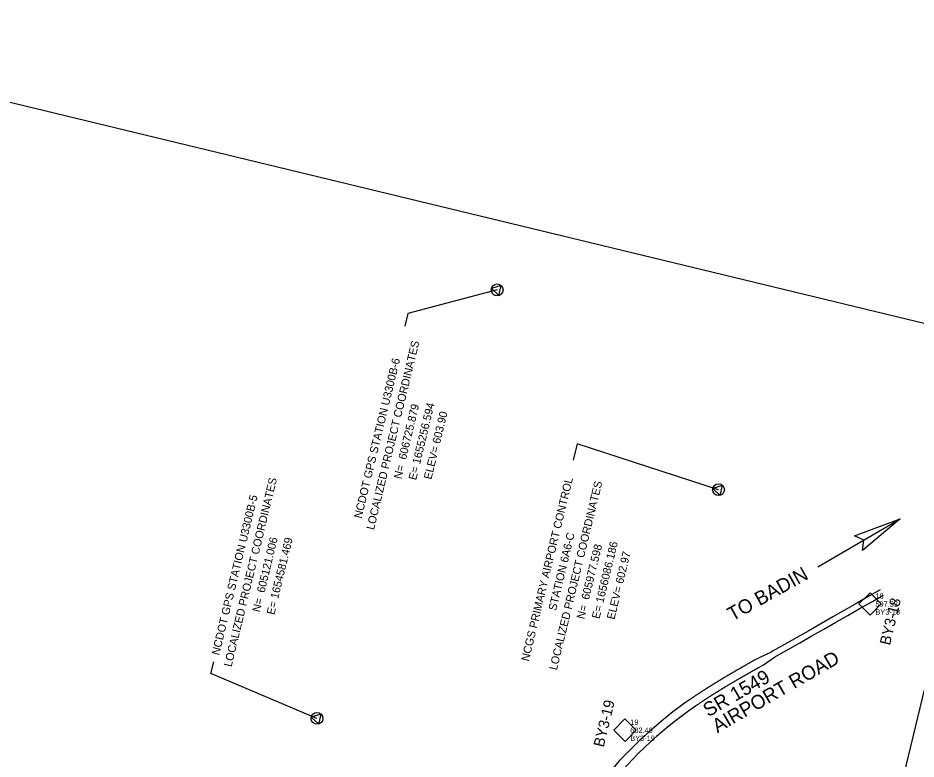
# Model space of a CAD drawing. Extents: x 1649669 to 1659218, y 588594 to 607900.
# Drawn here: x 1653461 to 1656826, y 604969 to 607744 of the extents above; entities that cross this region are included whole.
import ezdxf

# ---------------------------------------------------------------- set-up
doc = ezdxf.new("R2010")
doc.units = 0
for name, color, linetype in [('CTL NGS Horizontal CELL', 7, 'Continuous'), ('CTL NGS Horizontal Leader', 7, 'Continuous'), ('CTL NGS Horizontal Text', 7, 'Continuous'), ('CTL Sheet Border CELL', 7, 'Continuous'), ('CTL Sheet Notes CELL', 7, 'Continuous'), ('CTL Supplemental Horizontal and Vertical CELL', 7, 'Continuous'), ('CTL Supplemental Horizontal and Vertical Cogo Comment', 7, 'Continuous'), ('CTL Supplemental Horizontal and Vertical Cogo Elevation', 7, 'Continuous'), ('CTL Supplemental Horizontal and Vertical Cogo Number', 7, 'Continuous'), ('CTL Supplemental Horizontal and Vertical Text', 7, 'Continuous'), ('Default', 7, 'Continuous'), ('Exist Roads EOP', 7, 'Continuous'), ('Prop Terminator CELL', 7, 'Continuous'), ('Sheet Data Field CELL', 7, 'Continuous')]:
    doc.layers.add(name, color=color, linetype=linetype)

# ---------------------------------------------------------------- blocks, each defined once
blk = doc.blocks.new('CTL NGS HORIZONTAL')
at = {"layer": 'CTL NGS Horizontal CELL'}
blk.add_line((0, 0), (0, 0), dxfattribs=at)
blk.add_lwpolyline([(-0.064, -0.037), (0.064, -0.037), (0, 0.074), (-0.064, -0.037)], dxfattribs=at)
blk.add_circle((0, 0), 0.0738, dxfattribs=at)

msp = doc.modelspace()

# ---------------------------------------------------------------- linework, layer by layer
at = {"layer": 'CTL NGS Horizontal Leader'}
for points in [[(1655256.6, 606725.9), (1654921.9, 606637.9), (1654910.4, 606590.4)], [(1656086.2, 605977.6), (1655556.7, 606149.8), (1655541.9, 606088.2)], [(1654581.5, 605121), (1654184.1, 605289.7), (1654194.6, 605333.2)]]:
    msp.add_lwpolyline(points, dxfattribs=at)
at = {"layer": 'CTL Sheet Border CELL'}
msp.add_lwpolyline([(1652117.6, 607744.3), (1649668.6, 597600.9), (1656768.8, 595886.6), (1659217.9, 606030)], close=True, dxfattribs=at)
at = {"layer": 'CTL Sheet Notes CELL'}
msp.add_lwpolyline([(1656065.2, 601942.6), (1657135.7, 606376.1), (1658875.8, 605955.9), (1657805.4, 601522.5)], close=True, dxfattribs=at)
at = {"layer": 'CTL Supplemental Horizontal and Vertical CELL'}
for p, q in [((1656654.1, 605549.5), (1656654.1, 605549.5)), ((1655735.5, 605076.7), (1655735.5, 605076.7))]:
    msp.add_line(p, q, dxfattribs=at)
for points in [[(1656612.3, 605549.6), (1656654.3, 605591.6), (1656696.3, 605549.6), (1656654.3, 605507.6)], [(1655693.8, 605076.9), (1655735.7, 605118.8), (1655777.7, 605076.8), (1655735.8, 605034.9)]]:
    msp.add_lwpolyline(points, close=True, dxfattribs=at)
at = {"layer": 'Default'}
msp.add_line((1656457.8, 605688.9), (1656766.9, 605867.9), dxfattribs=at)
at = {"layer": 'Exist Roads EOP'}
for p, q in [((1656651.9, 605579.6), (1656606.4, 605553.5)), ((1656691.4, 605602), (1656651.9, 605579.6)), ((1656663.5, 605559.4), (1656702.8, 605582)), ((1656606.4, 605553.5), (1656560.3, 605527.1)), ((1656617.5, 605533.5), (1656663.5, 605559.4)), ((1656560.3, 605527.1), (1656514.7, 605501.3)), ((1656571.1, 605506.9), (1656617.5, 605533.5)), ((1656514.7, 605501.3), (1656469.5, 605475.6)), ((1656480.6, 605455.5), (1656526.2, 605481.3)), ((1656526.2, 605481.3), (1656571.1, 605506.9)), ((1656424.5, 605449.6), (1656379.4, 605424.2)), ((1656469.5, 605475.6), (1656424.5, 605449.6)), ((1656435.8, 605430), (1656480.6, 605455.5)), ((1656379.4, 605424.2), (1656334, 605398.3)), ((1656390.6, 605404.3), (1656435.8, 605430)), ((1656334, 605398.3), (1656288.7, 605372.9)), ((1656299.9, 605352.8), (1656344.9, 605378)), ((1656344.9, 605378), (1656390.6, 605404.3)), ((1656221.9, 605339.8), (1656239.2, 605349.6)), ((1656239.2, 605349.6), (1656284.8, 605370.7)), ((1656255.1, 605321.8), (1656296.2, 605350.7)), ((1656288.7, 605372.9), (1656284.8, 605370.7)), ((1656296.2, 605350.7), (1656299.9, 605352.8)), ((1656237.7, 605311.9), (1656255.1, 605321.8))]:
    msp.add_line(p, q, dxfattribs=at)
for radius, end in [(1616, 140.1492), (1584, 160.233)]:
    msp.add_arc((1656901, 603864.5), radius, 124.6758, end, dxfattribs=at)
for points in [[(1656221.9, 605339.8), (1656218.6, 605337.9), (1656215.3, 605336), (1656212, 605334.1), (1656208.7, 605332.3), (1656205.4, 605330.4), (1656202.1, 605328.5), (1656198.8, 605326.6), (1656195.6, 605324.8), (1656192.3, 605322.9), (1656189, 605321), (1656185.7, 605319.1), (1656182.4, 605317.2), (1656179.1, 605315.3), (1656175.8, 605313.5), (1656172.5, 605311.6), (1656169.2, 605309.7), (1656166, 605307.8), (1656162.7, 605305.9), (1656159.4, 605304), (1656156.1, 605302.1), (1656152.8, 605300.2), (1656149.5, 605298.3), (1656146.3, 605296.4), (1656143, 605294.5), (1656139.7, 605292.6), (1656136.4, 605290.7), (1656133.1, 605288.8), (1656129.9, 605286.8), (1656126.6, 605284.9), (1656123.3, 605283), (1656120, 605281.1), (1656116.8, 605279.1), (1656113.5, 605277.2), (1656110.2, 605275.2), (1656107, 605273.3), (1656103.7, 605271.4), (1656100.4, 605269.4), (1656097.2, 605267.4), (1656093.9, 605265.5), (1656090.6, 605263.5), (1656087.4, 605261.6), (1656084.1, 605259.6), (1656080.9, 605257.6), (1656077.6, 605255.6), (1656074.4, 605253.6), (1656071.1, 605251.6), (1656067.9, 605249.6), (1656064.7, 605247.6), (1656061.4, 605245.6), (1656058.2, 605243.6), (1656055, 605241.6), (1656051.7, 605239.6), (1656048.5, 605237.5), (1656045.3, 605235.5), (1656042.1, 605233.5), (1656038.9, 605231.4), (1656035.6, 605229.4), (1656032.4, 605227.3), (1656029.2, 605225.2), (1656026, 605223.2), (1656022.8, 605221.1), (1656019.6, 605219), (1656016.4, 605216.9), (1656013.3, 605214.8), (1656010.1, 605212.7), (1656006.9, 605210.6), (1656003.7, 605208.5), (1656000.5, 605206.4), (1655997.4, 605204.2), (1655994.2, 605202.1), (1655991.1, 605199.9), (1655987.9, 605197.8), (1655984.7, 605195.6), (1655981.6, 605193.5)], [(1656237.7, 605311.9), (1656234.4, 605310.1), (1656231.1, 605308.2), (1656227.8, 605306.3), (1656224.6, 605304.5), (1656221.3, 605302.6), (1656218, 605300.7), (1656214.7, 605298.8), (1656211.4, 605297), (1656208.1, 605295.1), (1656204.9, 605293.2), (1656201.6, 605291.3), (1656198.3, 605289.5), (1656195, 605287.6), (1656191.7, 605285.7), (1656188.5, 605283.8), (1656185.2, 605281.9), (1656181.9, 605280.1), (1656178.7, 605278.2), (1656175.4, 605276.3), (1656172.1, 605274.4), (1656168.8, 605272.5), (1656165.6, 605270.6), (1656162.3, 605268.7), (1656159.1, 605266.8), (1656155.8, 605264.9), (1656152.5, 605263), (1656149.3, 605261.1), (1656146, 605259.2), (1656142.8, 605257.3), (1656139.5, 605255.4), (1656136.3, 605253.5), (1656133, 605251.6), (1656129.8, 605249.7), (1656126.6, 605247.7), (1656123.3, 605245.8), (1656120.1, 605243.9), (1656116.9, 605242), (1656113.6, 605240), (1656110.4, 605238.1), (1656107.2, 605236.1), (1656104, 605234.2), (1656100.8, 605232.2), (1656097.5, 605230.3), (1656094.3, 605228.3), (1656091.1, 605226.4), (1656087.9, 605224.4), (1656084.7, 605222.4), (1656081.5, 605220.4), (1656078.3, 605218.5), (1656075.1, 605216.5), (1656071.9, 605214.5), (1656068.8, 605212.5), (1656065.6, 605210.5), (1656062.4, 605208.5), (1656059.2, 605206.5), (1656056.1, 605204.4), (1656052.9, 605202.4), (1656049.7, 605200.4), (1656046.6, 605198.4), (1656043.4, 605196.3), (1656040.3, 605194.3), (1656037.1, 605192.2), (1656034, 605190.2), (1656030.9, 605188.1), (1656027.7, 605186), (1656024.6, 605184), (1656021.5, 605181.9), (1656018.4, 605179.8), (1656015.3, 605177.7), (1656012.2, 605175.6), (1656009.1, 605173.5), (1656006, 605171.4), (1656002.9, 605169.3), (1655999.8, 605167.1)]]:
    msp.add_spline(points, degree=3, dxfattribs=at)
at = {"layer": 'Prop Terminator CELL'}
msp.add_lwpolyline([(1656595.6, 605804.5), (1656766.9, 605867.9), (1656626.3, 605749.5), (1656630.2, 605788.7)], close=True, dxfattribs=at)

# ---------------------------------------------------------------- block references
at = {"layer": 'CTL NGS Horizontal CELL', "xscale": 300, "yscale": 300, "rotation": -42.96908576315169}
for p in [(1655256.6, 606725.9), (1656086.2, 605977.6), (1654581.5, 605121)]:
    msp.add_blockref('CTL NGS HORIZONTAL', p, dxfattribs=at)

# ---------------------------------------------------------------- texts
at = {"layer": 'CTL NGS Horizontal Text'}
for s, p in [('LOCALIZED PROJECT COORDINATES', (1654794.9, 605825.2)), ('NCDOT GPS STATION U3300B-6', (1654748.7, 605868.1)), ('N=  606725.879', (1654897.5, 606015.7)), ('E= 1655256.594', (1654953.1, 606011.7)), ('ELEV= 603.90', (1655010.2, 606014)), ('LOCALIZED PROJECT COORDINATES', (1654261.3, 605312.2)), ('NCGS PRIMARY AIRPORT CONTROL', (1655375.2, 605332.9)), ('LOCALIZED PROJECT COORDINATES', (1655480.4, 605299.7)), ('NCDOT GPS STATION U3300B-5', (1654215.2, 605355.9)), ('STATION 6A6-C', (1655477.6, 605522.5)), ('N=  605121.006', (1654367.3, 605517)), ('E= 1654581.469', (1654421.5, 605507.1)), ('E= 1656086.186', (1655640, 605492)), ('N=  605977.598', (1655583.1, 605490.9)), ('ELEV= 602.97', (1655696, 605489.7))]:
    msp.add_text(s, height=30, rotation=76.4261, dxfattribs=at).set_placement(p)
at = {"layer": 'CTL Supplemental Horizontal and Vertical Cogo Comment'}
for s, p in [('BY3-18', (1656674.1, 605509.5)), ('BY3-19', (1655755.5, 605036.7))]:
    msp.add_text(s, height=20, dxfattribs=at).set_placement(p)
at = {"layer": 'CTL Supplemental Horizontal and Vertical Cogo Elevation'}
for s, p in [('597.32', (1656674.1, 605539.5)), ('602.49', (1655755.5, 605066.7))]:
    msp.add_text(s, height=20, dxfattribs=at).set_placement(p)
at = {"layer": 'CTL Supplemental Horizontal and Vertical Cogo Number'}
for s, p in [('18', (1656674.1, 605569.5)), ('19', (1655755.5, 605096.7))]:
    msp.add_text(s, height=20, dxfattribs=at).set_placement(p)
at = {"layer": 'CTL Supplemental Horizontal and Vertical Text'}
for s, p in [('BY3-18', (1656728.4, 605392.8)), ('BY3-19', (1655655.9, 605011))]:
    msp.add_text(s, height=40, rotation=76.4261, dxfattribs=at).set_placement(p)
at = {"layer": 'Sheet Data Field CELL'}
for s, height, rotation, p in [('TO BADIN', 52.5, 29.2392, (1656137.9, 605483.7)), ('AIRPORT ROAD', 52.501, 29.9638, (1656082, 605065.1)), ('SR 1549', 52.5, 29.9638, (1656047.6, 605124.7))]:
    msp.add_text(s, height=height, rotation=rotation, dxfattribs=at).set_placement(p)

doc.saveas('drawing.dxf')
